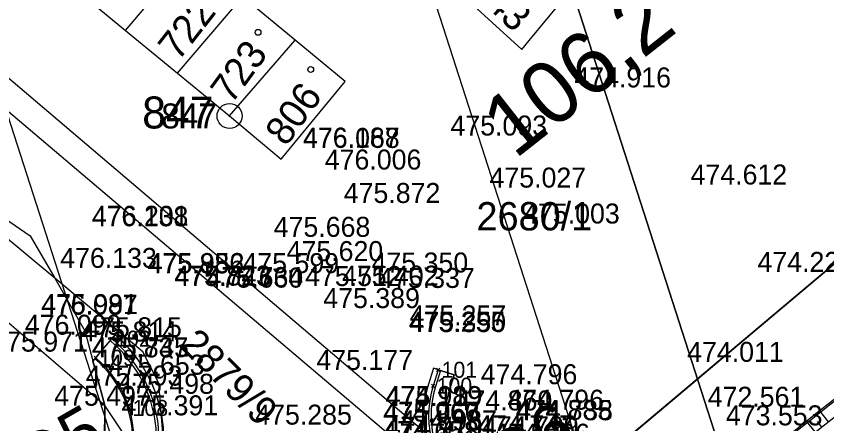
# Model space of a CAD drawing. Extents: x -758836 to -757729, y -1175316 to -1174366.
# Drawn here: x -758436.44 to -758387.77, y -1174826.39 to -1174801.92 of the extents above; entities that cross this region are included whole.
import ezdxf

# ---------------------------------------------------------------- set-up
doc = ezdxf.new("R2010")
doc.units = 0
for name, color, linetype in [('__NOR-dočasný zábor', 7, 'Continuous'), ('_NOR-návrh silná', 7, 'Continuous'), ('_NOR-návrh tenká', 7, 'Continuous'), ('_NOR-osa', 7, 'Continuous'), ('_NOR-pomocná', 7, 'Continuous'), ('_NOR-popis', 7, 'Continuous'), ('_NOR-sanace', 7, 'Continuous'), ('_NOR-svahy', 7, 'Continuous'), ('_vytyčený bod', 7, 'Continuous'), ('G_Obvod stavby', 7, 'Continuous'), ('Hranice parcel', 7, 'Continuous'), ('Parcelní čísla', 7, 'Continuous'), ('Vnitřní kresba', 7, 'Continuous'), ('Vrstva 61', 7, 'Continuous'), ('Vrstva 7', 7, 'Continuous'), ('Značky bodu BP', 7, 'Continuous'), ('Značky budov', 7, 'Continuous')]:
    doc.layers.add(name, color=color, linetype=linetype)

msp = doc.modelspace()

# ---------------------------------------------------------------- linework, layer by layer
at = {"layer": '__NOR-dočasný zábor'}
for p, q in [((-758431.833, -1174822.623), (-758430.506, -1174821.051)), ((-758431.12, -1174825.29), (-758431.833, -1174822.623)), ((-758411.39, -1174823.058), (-758411.69, -1174824.012)), ((-758411.104, -1174823.148), (-758411.39, -1174823.058)), ((-758410.96, -1174823.193), (-758411.104, -1174823.148)), ((-758410.15, -1174823.448), (-758410.96, -1174823.193)), ((-758410.449, -1174824.402), (-758410.15, -1174823.448)), ((-758431.14, -1174830.31), (-758431.12, -1174825.29))]:
    msp.add_line(p, q, dxfattribs=at)
for centre, radius, start, end in [((-758435.859, -1174827.393), 8.3, 341.6371, 49.8317), ((-758405.68, -1174825.901), 6.3, 162.5481, 188.8894), ((-758405.68, -1174825.901), 5, 162.5481, 212.3104)]:
    msp.add_arc(centre, radius, start, end, dxfattribs=at)
at = {"layer": '_NOR-návrh silná'}
msp.add_lwpolyline([(-758411.104, -1174823.148), (-758411.403, -1174824.102)], dxfattribs=at)
for centre, radius, start, end in [((-758435.859, -1174827.393), 8, 315.1499, 49.8317), ((-758435.859, -1174827.393), 6.5, 345.1172, 49.8317), ((-758405.68, -1174825.901), 6, 162.5481, 232.6885)]:
    msp.add_arc(centre, radius, start, end, dxfattribs=at)
at = {"layer": '_NOR-návrh tenká'}
for p, q in [((-758431.667, -1174822.426), (-758430.699, -1174821.28)), ((-758431.718, -1174822.487), (-758431.667, -1174822.426))]:
    msp.add_line(p, q, dxfattribs=at)
for points in [[(-758430.506, -1174821.051), (-758430.699, -1174821.28)], [(-758431.718, -1174822.487), (-758431.833, -1174822.623), (-758431.12, -1174825.29), (-758431.14, -1174830.31), (-758433.036, -1174831.952), (-758431.169, -1174833.809)], [(-758411.104, -1174823.148), (-758411.39, -1174823.058), (-758411.69, -1174824.012)], [(-758411.104, -1174823.148), (-758410.96, -1174823.193), (-758411.26, -1174824.147)], [(-758410.96, -1174823.193), (-758410.15, -1174823.448), (-758410.449, -1174824.402)]]:
    msp.add_lwpolyline(points, dxfattribs=at)
for centre, radius, start, end in [((-758205.34, -1175057.864), 295.6, 97.09776, 129.28488), ((-758205.34, -1175057.864), 294.75, 97.0979, 129.28474), ((-758205.34, -1175057.864), 291.3, 97.09848, 129.28417), ((-758205.34, -1175057.864), 290.55, 97.09861, 129.28404), ((-758205.34, -1175057.864), 293.75, 120.96729, 129.28457), ((-758205.34, -1175057.864), 292.25, 120.96729, 129.28432), ((-758435.859, -1174827.393), 8.3, 315.1499, 49.8317), ((-758435.859, -1174827.393), 7.85, 315.1499, 49.8317), ((-758435.859, -1174827.393), 6.42, 356.6281, 49.8317), ((-758405.68, -1174825.901), 6.3, 162.5481, 232.6885), ((-758405.68, -1174825.901), 5.85, 162.5481, 232.6885), ((-758405.68, -1174825.901), 5, 162.5481, 232.6885)]:
    msp.add_arc(centre, radius, start, end, dxfattribs=at)
at = {"layer": '_NOR-osa'}
msp.add_arc((-758205.34, -1175057.864), 293, 97.09819, 129.28445, dxfattribs=at)
at = {"layer": '_NOR-pomocná'}
for points in [[(-758417.595, -1174755.224), (-758317.652, -1174723.031), (-758272.123, -1174864.38), (-758372.066, -1174896.572)], [(-758517.538, -1174787.416), (-758417.595, -1174755.224), (-758372.066, -1174896.572), (-758472.009, -1174928.764)]]:
    msp.add_lwpolyline(points, close=True, dxfattribs=at)
at = {"layer": '_NOR-popis'}
for points in [[(-758411.267, -1174770.178), (-758420.309, -1174773.091), (-758401.541, -1174831.358)], [(-758436.507, -1174778.308), (-758445.549, -1174781.221), (-758425.724, -1174842.771)]]:
    msp.add_lwpolyline(points, dxfattribs=at)
at = {"layer": '_NOR-sanace'}
for radius, end in [(295.5, 129.28486), (290.5, 129.28403)]:
    msp.add_arc((-758205.34, -1175057.864), radius, 124.47202, end, dxfattribs=at)
at = {"layer": '_NOR-svahy'}
for points in [[(-758387.671, -1174826.276), (-758388.197, -1174825.608)], [(-758388.455, -1174826.896), (-758388.984, -1174826.23)], [(-758388.063, -1174826.586), (-758388.327, -1174826.252)]]:
    msp.add_lwpolyline(points, dxfattribs=at)
at = {"layer": '_vytyčený bod'}
for p, q in [((-758430.699, -1174821.28), (-758430.799, -1174821.18)), ((-758430.699, -1174821.28), (-758430.799, -1174821.38)), ((-758430.699, -1174821.28), (-758430.599, -1174821.18)), ((-758430.699, -1174821.28), (-758430.599, -1174821.38)), ((-758431.667, -1174822.426), (-758431.767, -1174822.326)), ((-758431.667, -1174822.426), (-758431.767, -1174822.526)), ((-758431.667, -1174822.426), (-758431.567, -1174822.326)), ((-758431.667, -1174822.426), (-758431.567, -1174822.526)), ((-758411.104, -1174823.148), (-758411.204, -1174823.048)), ((-758411.104, -1174823.148), (-758411.204, -1174823.248)), ((-758411.104, -1174823.148), (-758411.004, -1174823.048)), ((-758411.104, -1174823.148), (-758411.004, -1174823.248)), ((-758411.404, -1174824.102), (-758411.504, -1174824.002)), ((-758411.404, -1174824.102), (-758411.504, -1174824.202)), ((-758411.404, -1174824.102), (-758411.304, -1174824.002)), ((-758411.404, -1174824.102), (-758411.304, -1174824.202)), ((-758429.659, -1174825.441), (-758429.759, -1174825.341)), ((-758429.659, -1174825.441), (-758429.759, -1174825.541)), ((-758429.659, -1174825.441), (-758429.559, -1174825.341)), ((-758429.659, -1174825.441), (-758429.559, -1174825.541))]:
    msp.add_line(p, q, dxfattribs=at)
at = {"layer": 'G_Obvod stavby'}
for p, q in [((-758431.833, -1174822.623), (-758430.506, -1174821.051)), ((-758431.12, -1174825.29), (-758431.833, -1174822.623)), ((-758411.39, -1174823.058), (-758411.69, -1174824.012)), ((-758411.104, -1174823.148), (-758411.39, -1174823.058)), ((-758410.96, -1174823.193), (-758411.104, -1174823.148)), ((-758410.15, -1174823.448), (-758410.96, -1174823.193)), ((-758410.449, -1174824.402), (-758410.15, -1174823.448)), ((-758431.14, -1174830.31), (-758431.12, -1174825.29))]:
    msp.add_line(p, q, dxfattribs=at)
msp.add_lwpolyline([(-758392.72, -1174840.756), (-758391.23, -1174838.56), (-758368.37, -1174821.64), (-758340.31, -1174807.33), (-758320.27, -1174796.89), (-758301, -1174790.21), (-758267.96, -1174782.93), (-758224.96, -1174775.27), (-758184.87, -1174772.83), (-758142.71, -1174770.26), (-758089.84, -1174768.68), (-758106.02, -1174731.44), (-758149.09, -1174725.67), (-758199.62, -1174726.6), (-758225.76, -1174732.36), (-758252.17, -1174738.18), (-758254.97, -1174739.34), (-758266.58, -1174744.16), (-758279.45, -1174749.49), (-758302.42, -1174759.02), (-758331.68, -1174770.24), (-758367.17, -1174799.81), (-758405.64, -1174832.2)], dxfattribs=at)
for centre, radius, start, end in [((-758435.859, -1174827.393), 8.3, 341.6371, 49.8317), ((-758405.68, -1174825.901), 6.3, 162.5481, 188.8894), ((-758405.68, -1174825.901), 5, 162.5481, 212.3104)]:
    msp.add_arc(centre, radius, start, end, dxfattribs=at)
at = {"layer": 'Hranice parcel'}
for p, q in [((-758431.12, -1174825.29), (-758463.07, -1174797.97)), ((-758429.88, -1174802.77), (-758425.97, -1174798.15)), ((-758445.41, -1174798.39), (-758405.64, -1174832.2)), ((-758405.64, -1174832.2), (-758367.17, -1174799.81)), ((-758433, -1174800.2), (-758429.88, -1174802.77)), ((-758426.75, -1174805.34), (-758422.83, -1174800.74)), ((-758419.69, -1174803.35), (-758422.83, -1174800.74)), ((-758429.88, -1174802.77), (-758426.75, -1174805.34)), ((-758423.63, -1174807.91), (-758419.69, -1174803.35)), ((-758426.75, -1174805.34), (-758423.63, -1174807.91)), ((-758431.14, -1174830.31), (-758431.12, -1174825.29))]:
    msp.add_line(p, q, dxfattribs=at)
for points in [[(-758473.72, -1174788.92), (-758444.54, -1174808.96), (-758435.6, -1174815.1), (-758434.13, -1174817.65), (-758432.32, -1174820.8), (-758431.12, -1174825.29)], [(-758411.21, -1174799.23), (-758406.09, -1174803.91), (-758405.65, -1174803.38), (-758403.02, -1174800.2)], [(-758423.63, -1174807.91), (-758420.54, -1174810.5), (-758416.69, -1174805.84), (-758419.69, -1174803.35)], [(-758425.34, -1174833.98), (-758428.26, -1174829.59), (-758431.12, -1174825.29)]]:
    msp.add_lwpolyline(points, dxfattribs=at)
at = {"layer": 'Vnitřní kresba'}
for p, q in [((-758458.69, -1174789.18), (-758406.79, -1174833.17)), ((-758434.13, -1174817.65), (-758444.54, -1174808.96)), ((-758428.84, -1174822.07), (-758434.13, -1174817.65)), ((-758427.88, -1174823.96), (-758428.84, -1174822.07)), ((-758427.59, -1174827.47), (-758427.88, -1174823.96))]:
    msp.add_line(p, q, dxfattribs=at)
at = {"layer": 'Značky bodu BP'}
for radius in [0.75, 0.03]:
    msp.add_circle((-758423.63, -1174807.91), radius, dxfattribs=at)
at = {"layer": 'Značky budov'}
for centre in [(-758421.917, -1174802.889), (-758418.757, -1174805.119)]:
    msp.add_circle(centre, 0.175, dxfattribs=at)

# ---------------------------------------------------------------- texts
at = {"layer": '__NOR-dočasný zábor'}
for s, p in [('D5', (-758435.235, -1174830.11)), ('D6', (-758406.92, -1174829.928))]:
    msp.add_text(s, height=2.9088, rotation=30, dxfattribs=at).set_placement(p)
at = {"layer": '_vytyčený bod'}
for s, height, p in [('102', 0.9599, (-758430.499, -1174821.76)), ('102', 0.9596, (-758430.499, -1174821.76)), ('109', 0.9599, (-758431.467, -1174822.906)), ('109', 0.9596, (-758431.467, -1174822.906)), ('101', 0.9599, (-758410.904, -1174823.628)), ('101', 0.9596, (-758410.904, -1174823.628)), ('100', 0.9599, (-758411.204, -1174824.582)), ('100', 0.9596, (-758411.204, -1174824.582)), ('108', 0.9599, (-758429.459, -1174825.921)), ('108', 0.9596, (-758429.459, -1174825.921))]:
    msp.add_text(s, height=height, dxfattribs=at).set_placement(p)
at = {"layer": 'Parcelní čísla'}
for s, rotation, p in [('1043', 317, (-758410.223, -1174799.501)), ('722', 52, (-758426.706, -1174804.669)), ('723', 54, (-758423.513, -1174807.257)), ('806', 54, (-758420.233, -1174809.797)), ('2879/9', 315, (-758426.718, -1174821.722))]:
    msp.add_text(s, height=1.7, rotation=rotation, dxfattribs=at).set_placement(p)
msp.add_text('2680/1', height=1.7, dxfattribs=at).set_placement((-758408.805, -1174814.78))
at = {"layer": 'Vrstva 61'}
for s, p in [('474.916', (-758402.927, -1174806.196)), ('475.093', (-758410.367, -1174809.083)), ('476.187', (-758419.222, -1174809.806)), ('476.068', (-758419.216, -1174809.828)), ('476.006', (-758417.913, -1174811.126)), ('474.612', (-758395.951, -1174812.024)), ('475.027', (-758408.023, -1174812.21)), ('475.872', (-758416.775, -1174813.132)), ('475.003', (-758406.003, -1174814.367)), ('476.138', (-758431.907, -1174814.532)), ('476.201', (-758431.889, -1174814.502)), ('475.668', (-758420.979, -1174815.166)), ('475.620', (-758420.204, -1174816.621)), ('476.133', (-758433.797, -1174817.031)), ('475.886', (-758428.559, -1174817.36)), ('475.952', (-758428.531, -1174817.341)), ('475.599', (-758422.856, -1174817.344)), ('475.350', (-758415.103, -1174817.308)), ('474.226', (-758391.934, -1174817.272)), ('475.823', (-758426.95, -1174818.088)), ('475.743', (-758426.928, -1174818.117)), ('475.734', (-758425.015, -1174818.181)), ('475.660', (-758425.007, -1174818.215)), ('475.512', (-758419.094, -1174818.119)), ('475.402', (-758416.882, -1174818.094)), ('475.337', (-758414.707, -1174818.233)), ('476.087', (-758434.954, -1174819.84)), ('475.991', (-758434.929, -1174819.807)), ('475.389', (-758418.002, -1174819.442)), ('475.257', (-758412.821, -1174820.48)), ('476.099', (-758435.922, -1174821.041)), ('475.815', (-758432.295, -1174821.198)), ('475.255', (-758412.869, -1174820.859)), ('475.350', (-758412.829, -1174820.886)), ('475.814', (-758432.578, -1174821.442)), ('475.971', (-758437.936, -1174822.058)), ('475.837', (-758431.901, -1174822.401)), ('475.745', (-758431.869, -1174822.39)), ('474.011', (-758396.156, -1174822.671)), ('475.177', (-758418.416, -1174823.158)), ('475.653', (-758430.931, -1174823.439)), ('475.793', (-758432.264, -1174824.098)), ('474.796', (-758408.549, -1174824.014)), ('475.498', (-758430.367, -1174824.589)), ('475.497', (-758434.155, -1174825.305)), ('474.989', (-758414.273, -1174825.325)), ('475.119', (-758414.247, -1174825.331)), ('474.860', (-758410.053, -1174825.587)), ('474.796', (-758406.95, -1174825.543)), ('472.561', (-758394.923, -1174825.367)), ('475.391', (-758430.115, -1174825.882)), ('474.885', (-758406.458, -1174826.156)), ('475.285', (-758422.086, -1174826.439)), ('474.966', (-758414.42, -1174826.293)), ('475.067', (-758414.377, -1174826.258)), ('474.738', (-758406.411, -1174826.177)), ('473.553', (-758393.83, -1174826.484)), ('474.987', (-758413.38, -1174826.784)), ('474.747', (-758408.751, -1174827.084)), ('474.799', (-758408.471, -1174827.134)), ('474.658', (-758414.462, -1174827.424)), ('474.779', (-758414.267, -1174827.17)), ('474.910', (-758414.241, -1174827.165)), ('474.906', (-758407.796, -1174827.585))]:
    msp.add_text(s, height=1.2, dxfattribs=at).set_placement(p)
at = {"layer": 'Vrstva 7'}
msp.add_text('106,2', height=3.75, rotation=38.1935, dxfattribs=at).set_placement((-758406.498, -1174810.546))
at = {"layer": 'Značky bodu BP'}
for height, p in [(1.9192, (-758428.875, -1174808.66)), (1.5, (-758427.733, -1174808.66))]:
    msp.add_text('847', height=height, dxfattribs=at).set_placement(p)

doc.saveas('drawing.dxf')
